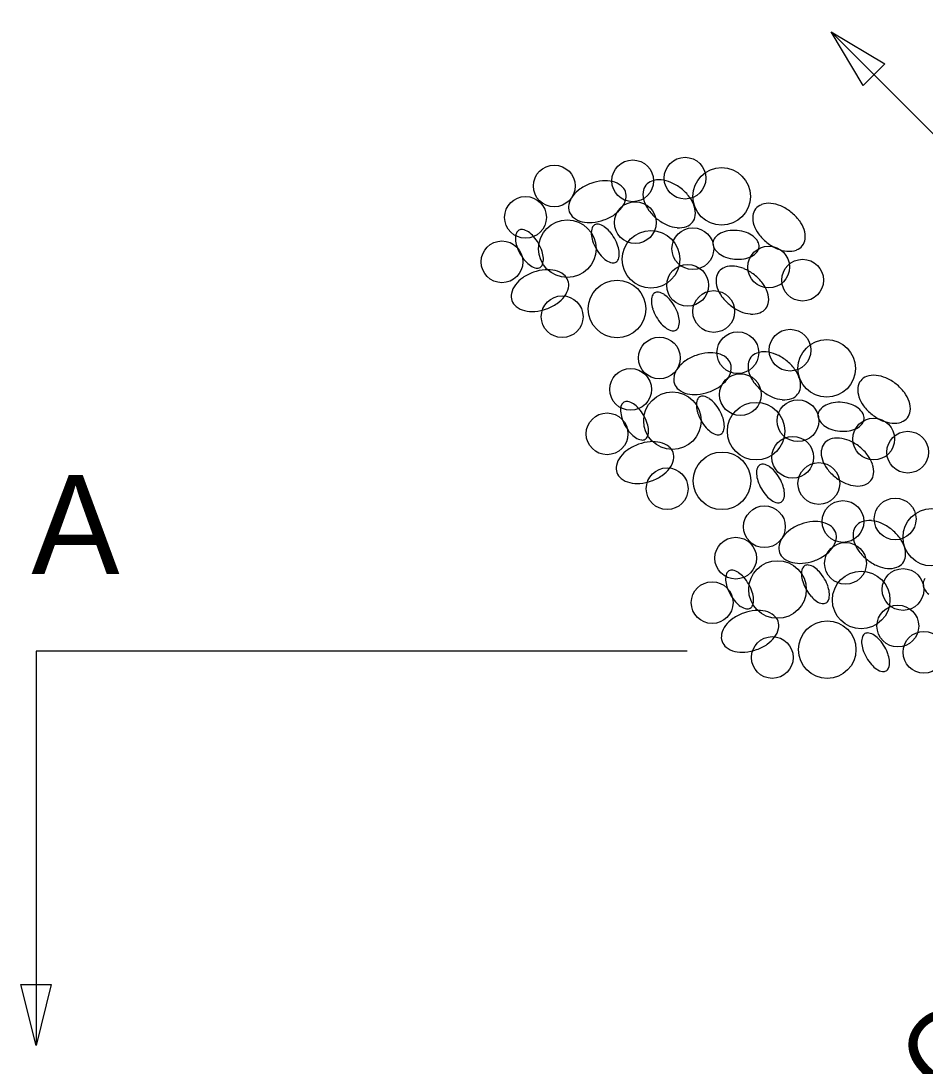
# Model space of a CAD drawing. Extents: x 9962.8 to 10024.8, y 9905.2 to 10002.8.
# Drawn here: x 9963.96 to 9976.35, y 9985.99 to 10000.3 of the extents above; entities that cross this region are included whole.
import ezdxf

# ---------------------------------------------------------------- set-up
doc = ezdxf.new("R2010")
doc.units = 0
for name, color, linetype in [('Default', 7, 'Continuous'), ('G-ANNO-TEXT', 7, 'Continuous'), ('G-ANNO-TTXT', 7, 'Continuous'), ('G-DETL-PATT', 7, 'Continuous')]:
    doc.layers.add(name, color=color, linetype=linetype)

# ---------------------------------------------------------------- blocks, each defined once
blk = doc.blocks.new('TERARR')
at = {"layer": 'Default'}
blk.add_lwpolyline([(-0.667, 0.167), (0, 0), (-0.667, -0.167)], close=True, dxfattribs=at)

msp = doc.modelspace()

# ---------------------------------------------------------------- linework, layer by layer
at = {"layer": 'G-ANNO-TEXT'}
for p, q in [((9982.487, 9992.728), (9975.059, 10000.157)), ((9973.087, 9991.677), (9964.17, 9991.677)), ((9964.17, 9991.677), (9964.17, 9986.277))]:
    msp.add_line(p, q, dxfattribs=at)
at = {"layer": 'G-DETL-PATT'}
for centre, radius in [((9971.268, 9998.044), 0.286), ((9972.343, 9998.115), 0.286), ((9973.059, 9998.151), 0.286), ((9973.56, 9997.901), 0.394), ((9970.874, 9997.614), 0.286), ((9972.378, 9997.543), 0.286), ((9971.447, 9997.185), 0.394), ((9973.166, 9997.185), 0.286), ((9972.593, 9997.041), 0.394), ((9970.552, 9997.006), 0.286), ((9974.205, 9996.934), 0.286), ((9974.67, 9996.755), 0.286), ((9973.095, 9996.684), 0.286), ((9972.128, 9996.361), 0.394), ((9973.453, 9996.326), 0.286), ((9971.376, 9996.254), 0.286), ((9973.782, 9995.761), 0.286), ((9974.498, 9995.796), 0.286), ((9972.708, 9995.689), 0.286), ((9975, 9995.546), 0.394), ((9972.314, 9995.259), 0.286), ((9973.818, 9995.188), 0.286), ((9972.887, 9994.83), 0.394), ((9974.033, 9994.687), 0.394), ((9974.606, 9994.83), 0.286), ((9971.992, 9994.651), 0.286), ((9975.644, 9994.579), 0.286), ((9974.534, 9994.329), 0.286), ((9976.11, 9994.4), 0.286), ((9973.567, 9994.007), 0.394), ((9972.815, 9993.899), 0.286), ((9974.892, 9993.971), 0.286), ((9975.222, 9993.45), 0.286), ((9975.938, 9993.485), 0.286), ((9974.147, 9993.378), 0.286), ((9976.439, 9993.235), 0.394), ((9973.753, 9992.948), 0.286), ((9975.257, 9992.877), 0.286), ((9974.326, 9992.519), 0.394), ((9975.472, 9992.376), 0.394), ((9976.045, 9992.519), 0.286), ((9973.431, 9992.34), 0.286), ((9975.974, 9992.018), 0.286), ((9975.007, 9991.696), 0.394), ((9974.255, 9991.588), 0.286), ((9976.332, 9991.66), 0.286)]:
    msp.add_circle(centre, radius, dxfattribs=at)
for centre, radius, start, end in [((9971.98, 9997.491), 0.625, 109.6611, 124.758), ((9971.98, 9997.491), 0.625, 94.5642, 109.6611), ((9971.965, 9997.674), 0.442, 76.5864, 94.5642), ((9971.996, 9997.803), 0.309, 52.1181, 76.5864), ((9972.077, 9997.907), 0.177, 19.6611, 52.1181), ((9972.661, 9997.944), 0.177, 141.6767, 174.1337), ((9972.661, 9997.944), 0.177, 109.2198, 141.6767), ((9972.704, 9997.82), 0.309, 84.7515, 109.2198), ((9972.692, 9997.687), 0.442, 66.7736, 84.7515), ((9972.619, 9997.519), 0.625, 51.6767, 66.7736), ((9971.769, 9997.722), 0.309, 142.7358, 167.2041), ((9971.875, 9997.641), 0.442, 124.758, 142.7358), ((9972.077, 9997.907), 0.177, 347.2041, 19.6611), ((9972.791, 9997.93), 0.309, 174.1337, 198.602), ((9972.619, 9997.519), 0.625, 36.5799, 51.6767), ((9972.767, 9997.628), 0.442, 18.602, 36.5799), ((9971.641, 9997.751), 0.177, 167.2041, 199.6611), ((9971.843, 9998.017), 0.442, 304.758, 322.7358), ((9971.949, 9997.936), 0.309, 322.7358, 347.2041), ((9972.918, 9997.973), 0.442, 198.602, 216.5799), ((9972.893, 9997.67), 0.309, 354.1337, 18.602), ((9974.165, 9997.621), 0.177, 109.2198, 141.6767), ((9974.208, 9997.498), 0.309, 84.7515, 109.2198), ((9974.196, 9997.365), 0.442, 66.7736, 84.7515), ((9974.123, 9997.196), 0.625, 51.6767, 66.7736), ((9971.641, 9997.751), 0.177, 199.6611, 232.1181), ((9971.722, 9997.855), 0.309, 232.1181, 256.5864), ((9971.738, 9998.167), 0.625, 289.6611, 304.758), ((9973.065, 9998.082), 0.625, 216.5798, 231.6767), ((9973.023, 9997.657), 0.177, 321.6767, 354.1337), ((9974.295, 9997.608), 0.309, 174.1337, 198.602), ((9974.165, 9997.621), 0.177, 141.6767, 174.1337), ((9974.123, 9997.196), 0.625, 36.5799, 51.6767), ((9971.753, 9997.984), 0.442, 256.5864, 274.5642), ((9971.985, 9997.399), 0.211, 159.8528, 183.557), ((9971.858, 9997.446), 0.0756, 119.7352, 159.8528), ((9971.738, 9998.167), 0.625, 274.5642, 289.6611), ((9971.858, 9997.446), 0.0756, 79.6177, 119.7352), ((9971.834, 9997.313), 0.211, 55.9134, 79.6177), ((9971.746, 9997.183), 0.367, 41.2446, 55.9134), ((9973.065, 9998.082), 0.625, 231.6767, 246.7736), ((9972.992, 9997.914), 0.442, 246.7736, 264.7515), ((9972.98, 9997.781), 0.309, 264.7515, 289.2198), ((9973.023, 9997.657), 0.177, 289.2198, 321.6767), ((9974.422, 9997.651), 0.442, 198.602, 216.5799), ((9974.271, 9997.306), 0.442, 18.602, 36.5799), ((9970.947, 9997.327), 0.211, 159.8528, 183.557), ((9971.103, 9997.337), 0.367, 183.557, 198.2258), ((9970.82, 9997.374), 0.0756, 119.7352, 159.8528), ((9970.82, 9997.374), 0.0756, 79.6177, 119.7352), ((9970.796, 9997.241), 0.211, 55.9134, 79.6177), ((9970.708, 9997.111), 0.367, 41.2446, 55.9134), ((9970.536, 9996.961), 0.596, 29.7352, 41.2446), ((9972.142, 9997.409), 0.367, 183.557, 198.2258), ((9971.575, 9997.032), 0.596, 29.7352, 41.2446), ((9971.575, 9997.032), 0.596, 18.2258, 29.7352), ((9973.567, 9997.256), 0.127, 141.1979, 174.8035), ((9973.653, 9997.187), 0.236, 116.7392, 141.1979), ((9973.704, 9997.086), 0.349, 99.2802, 116.7392), ((9973.729, 9996.93), 0.507, 84.8036, 99.2802), ((9973.729, 9996.93), 0.507, 70.3269, 84.8036), ((9973.782, 9997.079), 0.349, 52.8679, 70.3269), ((9973.851, 9997.169), 0.236, 28.4092, 52.8679), ((9974.569, 9997.76), 0.625, 216.5798, 231.6767), ((9974.527, 9997.335), 0.177, 321.6767, 354.1337), ((9974.397, 9997.348), 0.309, 354.1337, 18.602), ((9971.32, 9997.408), 0.596, 198.2258, 209.7352), ((9970.536, 9996.961), 0.596, 18.2258, 29.7352), ((9972.358, 9997.48), 0.596, 198.2258, 209.7352), ((9972.358, 9997.48), 0.596, 209.7352, 221.2446), ((9971.791, 9997.104), 0.367, 3.557, 18.2258), ((9973.567, 9997.256), 0.127, 174.8036, 208.4092), ((9973.664, 9997.308), 0.236, 208.4092, 232.8679), ((9973.947, 9997.221), 0.127, 321.1979, 354.8035), ((9973.947, 9997.221), 0.127, 354.8036, 28.4092), ((9974.569, 9997.76), 0.625, 231.6767, 246.7736), ((9974.496, 9997.591), 0.442, 246.7736, 264.7515), ((9974.484, 9997.459), 0.309, 264.7515, 289.2198), ((9974.527, 9997.335), 0.177, 289.2198, 321.6767), ((9971.32, 9997.408), 0.596, 209.7352, 221.2446), ((9970.753, 9997.032), 0.367, 3.557, 18.2258), ((9970.909, 9997.042), 0.211, 339.8528, 3.557), ((9972.187, 9997.33), 0.367, 221.2446, 235.9134), ((9972.099, 9997.2), 0.211, 235.9134, 259.6177), ((9972.075, 9997.067), 0.0756, 299.7352, 339.8528), ((9971.948, 9997.114), 0.211, 339.8528, 3.557), ((9973.732, 9997.398), 0.349, 232.8679, 250.3269), ((9973.785, 9997.547), 0.507, 250.3269, 264.8036), ((9973.785, 9997.547), 0.507, 264.8036, 279.2802), ((9973.811, 9997.391), 0.349, 279.2802, 296.7392), ((9973.862, 9997.29), 0.236, 296.7392, 321.1979), ((9971.148, 9997.258), 0.367, 221.2446, 235.9134), ((9971.061, 9997.128), 0.211, 235.9134, 259.6177), ((9971.192, 9996.274), 0.625, 94.5642, 109.6611), ((9971.036, 9996.995), 0.0756, 259.6177, 299.7352), ((9971.036, 9996.995), 0.0756, 299.7352, 339.8528), ((9971.178, 9996.456), 0.442, 76.5864, 94.5642), ((9971.209, 9996.586), 0.309, 52.1181, 76.5864), ((9972.075, 9997.067), 0.0756, 259.6177, 299.7352), ((9973.663, 9996.762), 0.177, 109.2198, 141.6767), ((9973.707, 9996.639), 0.309, 84.7515, 109.2198), ((9973.694, 9996.506), 0.442, 66.7736, 84.7515), ((9973.622, 9996.337), 0.625, 51.6767, 66.7736), ((9971.088, 9996.424), 0.442, 124.758, 142.7358), ((9971.192, 9996.274), 0.625, 109.6611, 124.758), ((9971.289, 9996.69), 0.177, 19.6611, 52.1181), ((9971.289, 9996.69), 0.177, 347.2041, 19.6611), ((9973.794, 9996.749), 0.309, 174.1337, 198.602), ((9973.663, 9996.762), 0.177, 141.6767, 174.1337), ((9973.622, 9996.337), 0.625, 36.5799, 51.6767), ((9970.982, 9996.505), 0.309, 142.7358, 167.2041), ((9971.161, 9996.719), 0.309, 322.7358, 347.2041), ((9973.92, 9996.792), 0.442, 198.602, 216.5799), ((9973.769, 9996.447), 0.442, 18.602, 36.5799), ((9970.854, 9996.534), 0.177, 167.2041, 199.6611), ((9970.854, 9996.534), 0.177, 199.6611, 232.1181), ((9971.055, 9996.8), 0.442, 304.758, 322.7358), ((9972.809, 9996.468), 0.211, 159.8528, 183.557), ((9972.965, 9996.478), 0.367, 183.557, 198.2258), ((9972.682, 9996.515), 0.0756, 119.7352, 159.8528), ((9972.682, 9996.515), 0.0756, 79.6177, 119.7352), ((9972.658, 9996.382), 0.211, 55.9134, 79.6177), ((9972.57, 9996.252), 0.367, 41.2446, 55.9134), ((9972.398, 9996.102), 0.596, 29.7352, 41.2446), ((9974.067, 9996.901), 0.625, 216.5798, 231.6767), ((9974.026, 9996.476), 0.177, 321.6767, 354.1337), ((9973.896, 9996.489), 0.309, 354.1337, 18.602), ((9970.934, 9996.638), 0.309, 232.1181, 256.5864), ((9970.965, 9996.767), 0.442, 256.5864, 274.5642), ((9970.951, 9996.95), 0.625, 274.5642, 289.6611), ((9970.951, 9996.95), 0.625, 289.6611, 304.758), ((9973.182, 9996.549), 0.596, 198.2258, 209.7352), ((9972.398, 9996.102), 0.596, 18.2258, 29.7352), ((9974.067, 9996.901), 0.625, 231.6767, 246.7736), ((9973.995, 9996.732), 0.442, 246.7736, 264.7515), ((9973.983, 9996.599), 0.309, 264.7515, 289.2198), ((9974.026, 9996.476), 0.177, 289.2198, 321.6767), ((9973.182, 9996.549), 0.596, 209.7352, 221.2446), ((9972.615, 9996.173), 0.367, 3.557, 18.2258), ((9972.771, 9996.183), 0.211, 339.8528, 3.557), ((9973.01, 9996.399), 0.367, 221.2446, 235.9134), ((9972.923, 9996.269), 0.211, 235.9134, 259.6177), ((9972.898, 9996.136), 0.0756, 259.6177, 299.7352), ((9972.898, 9996.136), 0.0756, 299.7352, 339.8528), ((9973.42, 9995.136), 0.625, 94.5642, 109.6611), ((9973.405, 9995.319), 0.442, 76.5864, 94.5642), ((9973.436, 9995.449), 0.309, 52.1181, 76.5864), ((9974.1, 9995.589), 0.177, 109.2198, 141.6767), ((9974.143, 9995.465), 0.309, 84.7515, 109.2198), ((9974.131, 9995.332), 0.442, 66.7736, 84.7515), ((9974.059, 9995.164), 0.625, 51.6767, 66.7736), ((9973.315, 9995.287), 0.442, 124.758, 142.7358), ((9973.42, 9995.136), 0.625, 109.6611, 124.758), ((9973.516, 9995.552), 0.177, 19.6611, 52.1181), ((9973.516, 9995.552), 0.177, 347.2041, 19.6611), ((9974.231, 9995.575), 0.309, 174.1337, 198.602), ((9974.1, 9995.589), 0.177, 141.6767, 174.1337), ((9974.059, 9995.164), 0.625, 36.5799, 51.6767), ((9973.209, 9995.367), 0.309, 142.7358, 167.2041), ((9973.389, 9995.581), 0.309, 322.7358, 347.2041), ((9974.357, 9995.618), 0.442, 198.602, 216.5799), ((9974.206, 9995.273), 0.442, 18.602, 36.5799), ((9975.647, 9995.143), 0.309, 84.7515, 109.2198), ((9975.635, 9995.01), 0.442, 66.7736, 84.7515), ((9973.081, 9995.396), 0.177, 167.2041, 199.6611), ((9973.081, 9995.396), 0.177, 199.6611, 232.1181), ((9973.282, 9995.662), 0.442, 304.758, 322.7358), ((9974.504, 9995.727), 0.625, 216.5798, 231.6767), ((9974.333, 9995.316), 0.309, 354.1337, 18.602), ((9975.604, 9995.267), 0.177, 141.6767, 174.1337), ((9975.604, 9995.267), 0.177, 109.2198, 141.6767), ((9975.563, 9994.842), 0.625, 51.6767, 66.7736), ((9975.563, 9994.842), 0.625, 36.5799, 51.6767), ((9973.162, 9995.5), 0.309, 232.1181, 256.5864), ((9973.192, 9995.63), 0.442, 256.5864, 274.5642), ((9973.178, 9995.812), 0.625, 274.5642, 289.6611), ((9973.298, 9995.091), 0.0756, 79.6177, 119.7352), ((9973.274, 9994.958), 0.211, 55.9134, 79.6177), ((9973.178, 9995.812), 0.625, 289.6611, 304.758), ((9974.504, 9995.727), 0.625, 231.6767, 246.7736), ((9974.463, 9995.302), 0.177, 289.2198, 321.6767), ((9974.463, 9995.302), 0.177, 321.6767, 354.1337), ((9975.735, 9995.253), 0.309, 174.1337, 198.602), ((9975.71, 9994.951), 0.442, 18.602, 36.5799), ((9972.386, 9994.973), 0.211, 159.8528, 183.557), ((9972.26, 9995.019), 0.0756, 119.7352, 159.8528), ((9972.26, 9995.019), 0.0756, 79.6177, 119.7352), ((9972.235, 9994.886), 0.211, 55.9134, 79.6177), ((9972.147, 9994.757), 0.367, 41.2446, 55.9134), ((9973.425, 9995.044), 0.211, 159.8528, 183.557), ((9973.581, 9995.054), 0.367, 183.557, 198.2258), ((9973.298, 9995.091), 0.0756, 119.7352, 159.8528), ((9973.186, 9994.828), 0.367, 41.2446, 55.9134), ((9973.014, 9994.678), 0.596, 29.7352, 41.2446), ((9974.432, 9995.559), 0.442, 246.7736, 264.7515), ((9974.42, 9995.426), 0.309, 264.7515, 289.2198), ((9975.092, 9994.832), 0.236, 116.7392, 141.1979), ((9975.143, 9994.731), 0.349, 99.2802, 116.7392), ((9975.169, 9994.576), 0.507, 84.8036, 99.2802), ((9975.169, 9994.576), 0.507, 70.3269, 84.8036), ((9975.222, 9994.724), 0.349, 52.8679, 70.3269), ((9975.861, 9995.296), 0.442, 198.602, 216.5799), ((9976.008, 9995.405), 0.625, 216.5798, 231.6767), ((9975.837, 9994.993), 0.309, 354.1337, 18.602), ((9972.543, 9994.982), 0.367, 183.557, 198.2258), ((9971.976, 9994.606), 0.596, 29.7352, 41.2446), ((9971.976, 9994.606), 0.596, 18.2258, 29.7352), ((9973.798, 9995.125), 0.596, 198.2258, 209.7352), ((9973.014, 9994.678), 0.596, 18.2258, 29.7352), ((9975.007, 9994.901), 0.127, 174.8036, 208.4092), ((9975.007, 9994.901), 0.127, 141.1979, 174.8035), ((9975.29, 9994.814), 0.236, 28.4092, 52.8679), ((9975.386, 9994.866), 0.127, 354.8036, 28.4092), ((9976.008, 9995.405), 0.625, 231.6767, 246.7736), ((9975.967, 9994.98), 0.177, 321.6767, 354.1337), ((9972.759, 9995.054), 0.596, 198.2258, 209.7352), ((9972.759, 9995.054), 0.596, 209.7352, 221.2446), ((9972.193, 9994.677), 0.367, 3.557, 18.2258), ((9973.798, 9995.125), 0.596, 209.7352, 221.2446), ((9973.626, 9994.975), 0.367, 221.2446, 235.9134), ((9973.231, 9994.749), 0.367, 3.557, 18.2258), ((9973.387, 9994.759), 0.211, 339.8528, 3.557), ((9975.103, 9994.953), 0.236, 208.4092, 232.8679), ((9975.172, 9995.043), 0.349, 232.8679, 250.3269), ((9975.301, 9994.935), 0.236, 296.7392, 321.1979), ((9975.386, 9994.866), 0.127, 321.1979, 354.8035), ((9975.936, 9995.237), 0.442, 246.7736, 264.7515), ((9975.924, 9995.104), 0.309, 264.7515, 289.2198), ((9975.967, 9994.98), 0.177, 289.2198, 321.6767), ((9972.588, 9994.903), 0.367, 221.2446, 235.9134), ((9972.5, 9994.774), 0.211, 235.9134, 259.6177), ((9972.476, 9994.641), 0.0756, 299.7352, 339.8528), ((9972.349, 9994.687), 0.211, 339.8528, 3.557), ((9973.539, 9994.845), 0.211, 235.9134, 259.6177), ((9973.514, 9994.712), 0.0756, 259.6177, 299.7352), ((9973.514, 9994.712), 0.0756, 299.7352, 339.8528), ((9975.146, 9994.284), 0.309, 84.7515, 109.2198), ((9975.225, 9995.192), 0.507, 250.3269, 264.8036), ((9975.134, 9994.151), 0.442, 66.7736, 84.7515), ((9975.225, 9995.192), 0.507, 264.8036, 279.2802), ((9975.25, 9995.036), 0.349, 279.2802, 296.7392), ((9972.632, 9993.919), 0.625, 109.6611, 124.758), ((9972.632, 9993.919), 0.625, 94.5642, 109.6611), ((9972.476, 9994.641), 0.0756, 259.6177, 299.7352), ((9972.617, 9994.102), 0.442, 76.5864, 94.5642), ((9972.648, 9994.232), 0.309, 52.1181, 76.5864), ((9972.729, 9994.335), 0.177, 19.6611, 52.1181), ((9975.103, 9994.408), 0.177, 141.6767, 174.1337), ((9975.103, 9994.408), 0.177, 109.2198, 141.6767), ((9975.062, 9993.983), 0.625, 51.6767, 66.7736), ((9975.062, 9993.983), 0.625, 36.5799, 51.6767), ((9972.421, 9994.15), 0.309, 142.7358, 167.2041), ((9972.527, 9994.07), 0.442, 124.758, 142.7358), ((9972.729, 9994.335), 0.177, 347.2041, 19.6611), ((9975.233, 9994.394), 0.309, 174.1337, 198.602), ((9975.209, 9994.092), 0.442, 18.602, 36.5799), ((9972.293, 9994.179), 0.177, 167.2041, 199.6611), ((9972.495, 9994.445), 0.442, 304.758, 322.7358), ((9972.601, 9994.364), 0.309, 322.7358, 347.2041), ((9974.249, 9994.114), 0.211, 159.8528, 183.557), ((9974.122, 9994.16), 0.0756, 119.7352, 159.8528), ((9974.122, 9994.16), 0.0756, 79.6177, 119.7352), ((9974.097, 9994.027), 0.211, 55.9134, 79.6177), ((9974.009, 9993.897), 0.367, 41.2446, 55.9134), ((9975.36, 9994.437), 0.442, 198.602, 216.5799), ((9975.507, 9994.546), 0.625, 216.5798, 231.6767), ((9975.335, 9994.134), 0.309, 354.1337, 18.602), ((9972.293, 9994.179), 0.177, 199.6611, 232.1181), ((9972.374, 9994.283), 0.309, 232.1181, 256.5864), ((9972.39, 9994.595), 0.625, 289.6611, 304.758), ((9974.405, 9994.123), 0.367, 183.557, 198.2258), ((9973.838, 9993.747), 0.596, 29.7352, 41.2446), ((9973.838, 9993.747), 0.596, 18.2258, 29.7352), ((9975.507, 9994.546), 0.625, 231.6767, 246.7736), ((9975.466, 9994.121), 0.177, 321.6767, 354.1337), ((9972.405, 9994.413), 0.442, 256.5864, 274.5642), ((9972.39, 9994.595), 0.625, 274.5642, 289.6611), ((9974.622, 9994.195), 0.596, 198.2258, 209.7352), ((9974.622, 9994.195), 0.596, 209.7352, 221.2446), ((9974.055, 9993.818), 0.367, 3.557, 18.2258), ((9975.435, 9994.378), 0.442, 246.7736, 264.7515), ((9975.422, 9994.245), 0.309, 264.7515, 289.2198), ((9975.466, 9994.121), 0.177, 289.2198, 321.6767), ((9974.45, 9994.044), 0.367, 221.2446, 235.9134), ((9974.362, 9993.915), 0.211, 235.9134, 259.6177), ((9974.338, 9993.782), 0.0756, 299.7352, 339.8528), ((9974.211, 9993.828), 0.211, 339.8528, 3.557), ((9974.338, 9993.782), 0.0756, 259.6177, 299.7352), ((9974.859, 9992.825), 0.625, 94.5642, 109.6611), ((9974.844, 9993.008), 0.442, 76.5864, 94.5642), ((9975.54, 9993.278), 0.177, 109.2198, 141.6767), ((9975.583, 9993.154), 0.309, 84.7515, 109.2198), ((9975.571, 9993.021), 0.442, 66.7736, 84.7515), ((9974.755, 9992.976), 0.442, 124.758, 142.7358), ((9974.859, 9992.825), 0.625, 109.6611, 124.758), ((9974.875, 9993.137), 0.309, 52.1181, 76.5864), ((9974.956, 9993.241), 0.177, 19.6611, 52.1181), ((9975.54, 9993.278), 0.177, 141.6767, 174.1337), ((9975.498, 9992.853), 0.625, 51.6767, 66.7736), ((9975.498, 9992.853), 0.625, 36.5799, 51.6767), ((9974.648, 9993.056), 0.309, 142.7358, 167.2041), ((9974.828, 9993.27), 0.309, 322.7358, 347.2041), ((9974.956, 9993.241), 0.177, 347.2041, 19.6611), ((9975.67, 9993.264), 0.309, 174.1337, 198.602), ((9975.797, 9993.307), 0.442, 198.602, 216.5799), ((9975.646, 9992.962), 0.442, 18.602, 36.5799), ((9974.521, 9993.085), 0.177, 167.2041, 199.6611), ((9974.521, 9993.085), 0.177, 199.6611, 232.1181), ((9974.722, 9993.351), 0.442, 304.758, 322.7358), ((9975.944, 9993.416), 0.625, 216.5798, 231.6767), ((9975.772, 9993.004), 0.309, 354.1337, 18.602), ((9974.601, 9993.189), 0.309, 232.1181, 256.5864), ((9974.632, 9993.319), 0.442, 256.5864, 274.5642), ((9974.617, 9993.501), 0.625, 274.5642, 289.6611), ((9974.617, 9993.501), 0.625, 289.6611, 304.758), ((9975.944, 9993.416), 0.625, 231.6767, 246.7736), ((9975.903, 9992.991), 0.177, 289.2198, 321.6767), ((9975.903, 9992.991), 0.177, 321.6767, 354.1337), ((9973.826, 9992.662), 0.211, 159.8528, 183.557), ((9973.699, 9992.708), 0.0756, 119.7352, 159.8528), ((9973.699, 9992.708), 0.0756, 79.6177, 119.7352), ((9973.675, 9992.575), 0.211, 55.9134, 79.6177), ((9973.587, 9992.445), 0.367, 41.2446, 55.9134), ((9974.864, 9992.733), 0.211, 159.8528, 183.557), ((9974.738, 9992.78), 0.0756, 119.7352, 159.8528), ((9974.738, 9992.78), 0.0756, 79.6177, 119.7352), ((9974.713, 9992.647), 0.211, 55.9134, 79.6177), ((9974.625, 9992.517), 0.367, 41.2446, 55.9134), ((9974.454, 9992.367), 0.596, 29.7352, 41.2446), ((9975.872, 9993.248), 0.442, 246.7736, 264.7515), ((9975.859, 9993.115), 0.309, 264.7515, 289.2198), ((9973.982, 9992.671), 0.367, 183.557, 198.2258), ((9973.415, 9992.295), 0.596, 29.7352, 41.2446), ((9973.415, 9992.295), 0.596, 18.2258, 29.7352), ((9975.021, 9992.743), 0.367, 183.557, 198.2258), ((9975.237, 9992.814), 0.596, 198.2258, 209.7352), ((9974.454, 9992.367), 0.596, 18.2258, 29.7352), ((9976.446, 9992.59), 0.127, 141.1979, 174.8035), ((9976.446, 9992.59), 0.127, 174.8036, 208.4092), ((9974.199, 9992.743), 0.596, 198.2258, 209.7352), ((9974.199, 9992.743), 0.596, 209.7352, 221.2446), ((9973.632, 9992.366), 0.367, 3.557, 18.2258), ((9975.237, 9992.814), 0.596, 209.7352, 221.2446), ((9974.671, 9992.438), 0.367, 3.557, 18.2258), ((9974.827, 9992.448), 0.211, 339.8528, 3.557), ((9976.543, 9992.642), 0.236, 208.4092, 232.8679), ((9974.027, 9992.592), 0.367, 221.2446, 235.9134), ((9973.915, 9992.33), 0.0756, 299.7352, 339.8528), ((9973.788, 9992.376), 0.211, 339.8528, 3.557), ((9975.066, 9992.664), 0.367, 221.2446, 235.9134), ((9974.978, 9992.534), 0.211, 235.9134, 259.6177), ((9974.954, 9992.401), 0.0756, 259.6177, 299.7352), ((9974.954, 9992.401), 0.0756, 299.7352, 339.8528), ((9974.071, 9991.608), 0.625, 109.6611, 124.758), ((9973.94, 9992.463), 0.211, 235.9134, 259.6177), ((9974.071, 9991.608), 0.625, 94.5642, 109.6611), ((9973.915, 9992.33), 0.0756, 259.6177, 299.7352), ((9974.057, 9991.791), 0.442, 76.5864, 94.5642), ((9974.088, 9991.92), 0.309, 52.1181, 76.5864), ((9974.168, 9992.024), 0.177, 19.6611, 52.1181), ((9973.861, 9991.839), 0.309, 142.7358, 167.2041), ((9973.967, 9991.759), 0.442, 124.758, 142.7358), ((9974.168, 9992.024), 0.177, 347.2041, 19.6611), ((9973.733, 9991.868), 0.177, 167.2041, 199.6611), ((9974.04, 9992.053), 0.309, 322.7358, 347.2041), ((9975.688, 9991.802), 0.211, 159.8528, 183.557), ((9975.561, 9991.849), 0.0756, 119.7352, 159.8528), ((9975.561, 9991.849), 0.0756, 79.6177, 119.7352), ((9975.537, 9991.716), 0.211, 55.9134, 79.6177), ((9975.449, 9991.586), 0.367, 41.2446, 55.9134), ((9973.733, 9991.868), 0.177, 199.6611, 232.1181), ((9973.813, 9991.972), 0.309, 232.1181, 256.5864), ((9973.83, 9992.284), 0.625, 289.6611, 304.758), ((9973.934, 9992.134), 0.442, 304.758, 322.7358), ((9975.844, 9991.812), 0.367, 183.557, 198.2258), ((9975.277, 9991.436), 0.596, 29.7352, 41.2446), ((9975.277, 9991.436), 0.596, 18.2258, 29.7352), ((9973.844, 9992.102), 0.442, 256.5864, 274.5642), ((9973.83, 9992.284), 0.625, 274.5642, 289.6611), ((9976.061, 9991.884), 0.596, 198.2258, 209.7352), ((9976.061, 9991.884), 0.596, 209.7352, 221.2446), ((9975.494, 9991.507), 0.367, 3.557, 18.2258), ((9975.89, 9991.733), 0.367, 221.2446, 235.9134), ((9975.777, 9991.47), 0.0756, 299.7352, 339.8528), ((9975.65, 9991.517), 0.211, 339.8528, 3.557), ((9975.802, 9991.603), 0.211, 235.9134, 259.6177), ((9975.777, 9991.47), 0.0756, 259.6177, 299.7352)]:
    msp.add_arc(centre, radius, start, end, dxfattribs=at)

# ---------------------------------------------------------------- block references
at = {"layer": 'G-ANNO-TEXT'}
for p, xscale, yscale, rotation in [((9975.059, 10000.157), 1.2499199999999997, 1.2499200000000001, 134.9962980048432), ((9964.17, 9986.277), 1.24992, 1.24992, -90)]:
    msp.add_blockref('TERARR', p, dxfattribs=dict(at, xscale=xscale, yscale=yscale, rotation=rotation))

# ---------------------------------------------------------------- texts
msp.add_text('SLOPE', height=1.044, rotation=45, dxfattribs=at).set_placement((9975.425, 9984.27))
at = {"layer": 'G-ANNO-TTXT'}
msp.add_text('A', height=1.356, dxfattribs=at).set_placement((9964.105, 9992.73))

doc.saveas('drawing.dxf')
